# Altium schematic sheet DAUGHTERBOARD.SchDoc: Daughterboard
size A3; DocumentNumber: 3; SheetNumber: 3; SheetTotal: 6
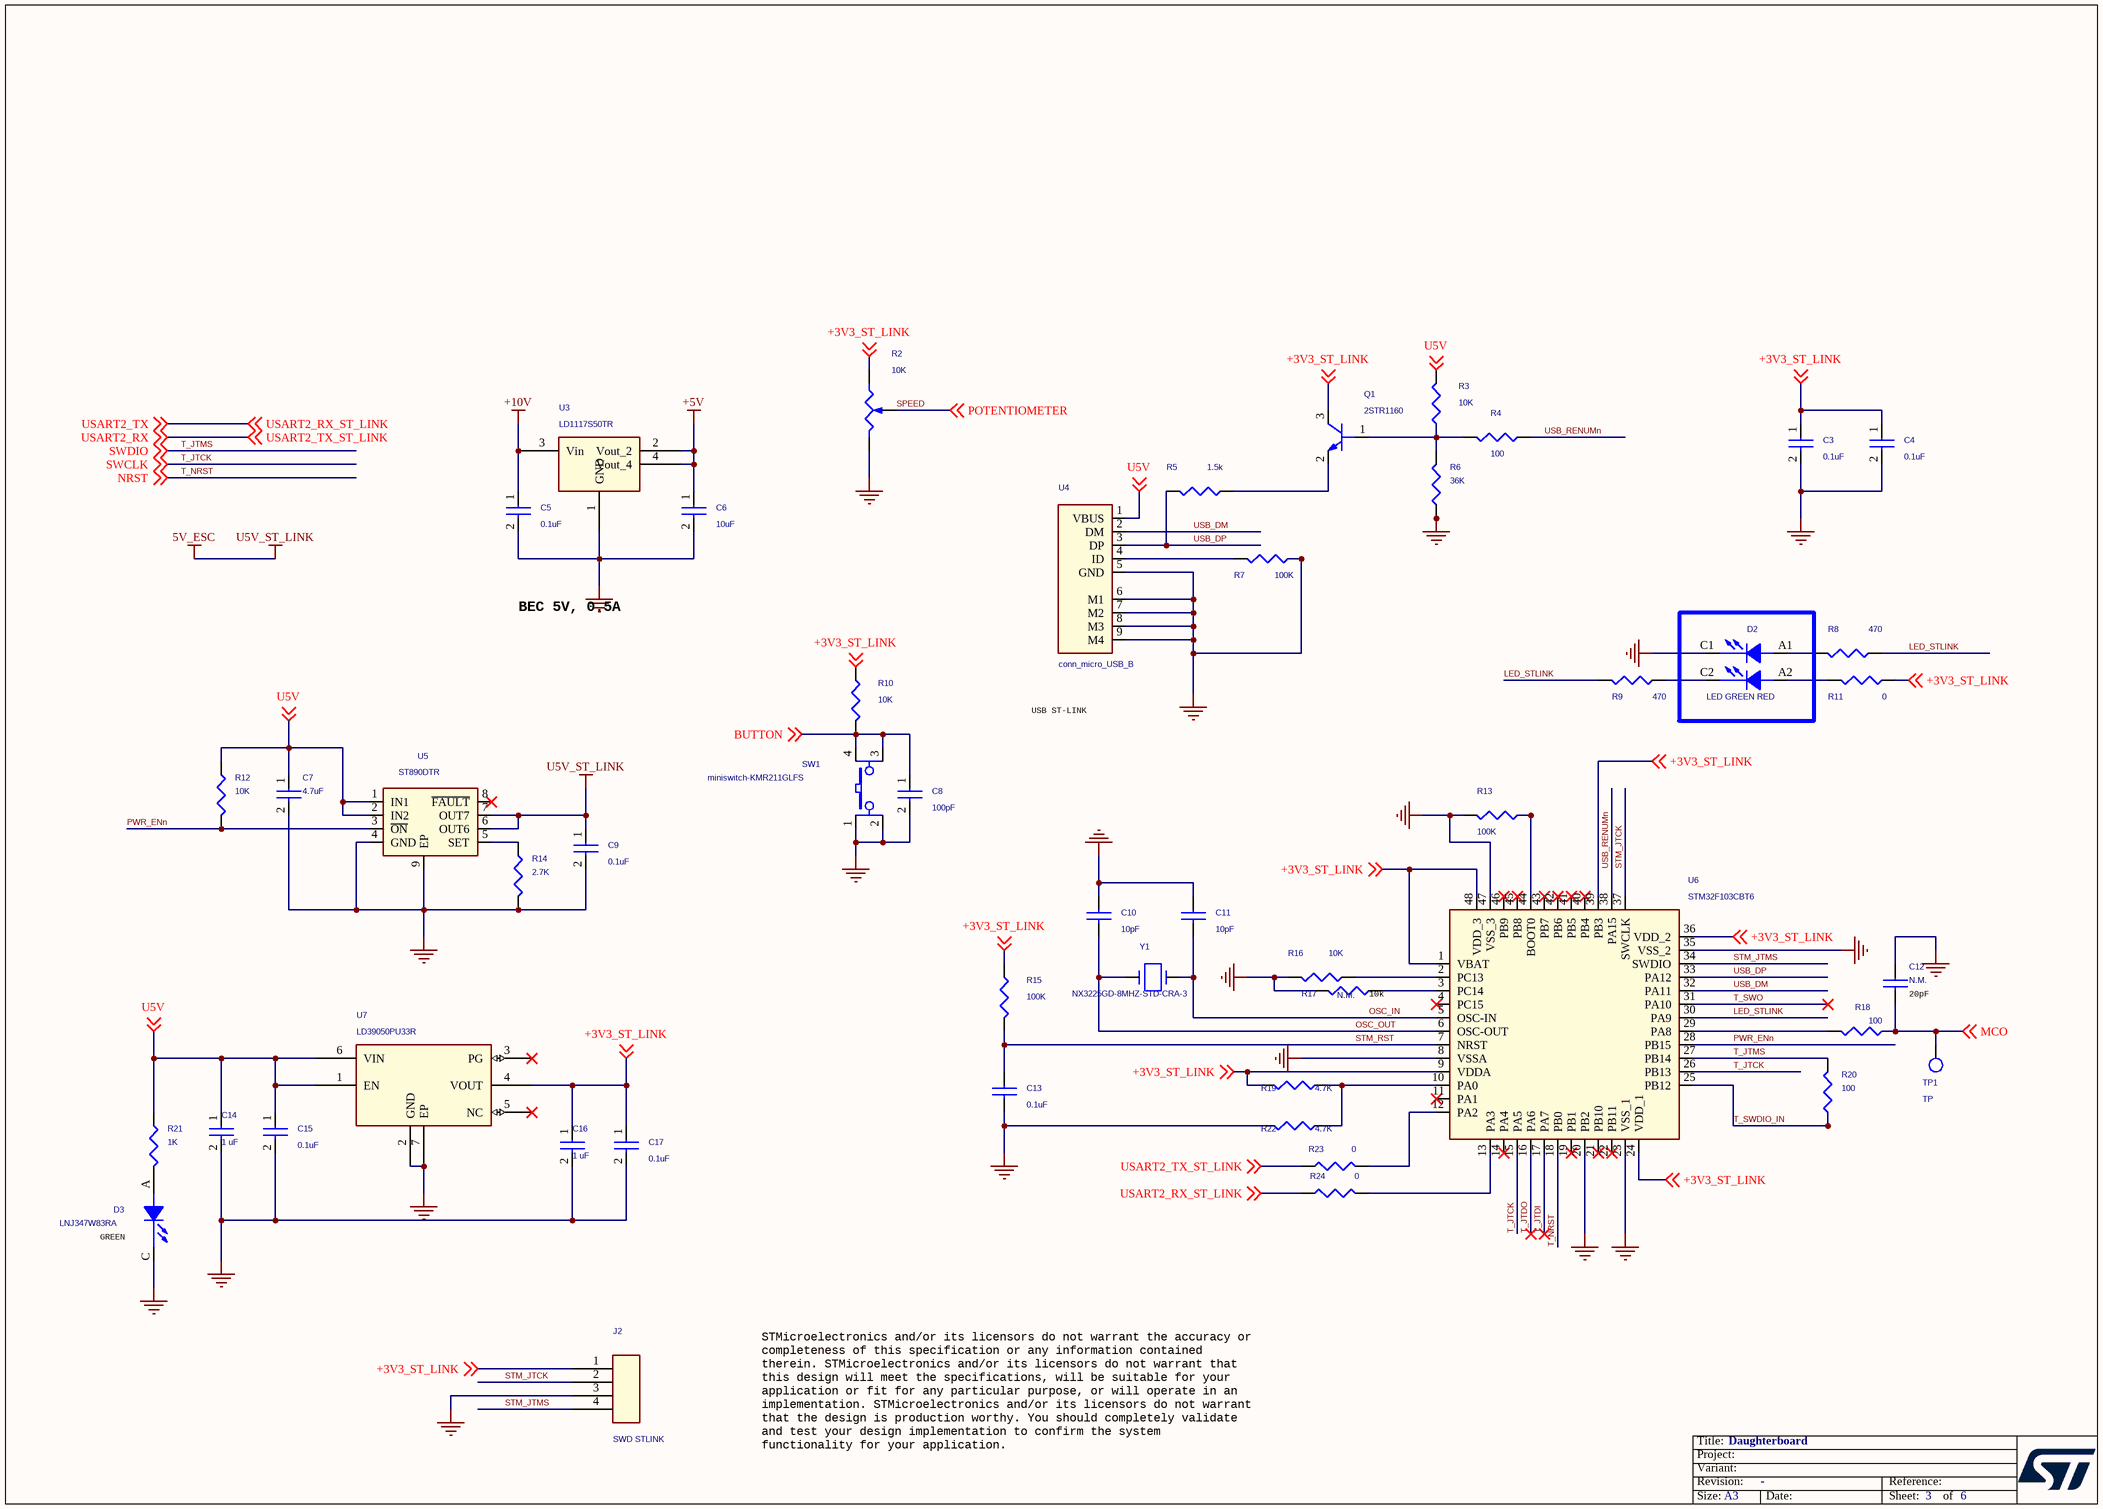
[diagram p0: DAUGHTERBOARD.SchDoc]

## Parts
C3  0.1uF  [C_0402]
C4  0.1uF  [C_0402]
C5  0.1uF  [C_0402]
C6  10uF  [C_0805]
C7  4.7uF  [C_0805]
C8  100pF  [C_0402]
C9  0.1uF  [C_0402]
C10  10pF  [C_0402]
C11  10pF  [C_0402]
C12  N.M.  [C_0402]
C13  0.1uF  [C_0402]
C14  1 uF  [C_0603]
C15  0.1uF  [C_0603]
C16  1 uF  [C_0603]
C17  0.1uF  [C_0402]
D2  LED GREEN RED  [Led_bicolor_3528-PLCC-4]
D3  LNJ347W83RA  [D_0402_Led_green]
J2  SWD STLINK  [strip4_100m_v]
Q1  2STR1160  [sot23-3p97_255x140l40x40n]
R2  10K  [trimmer-3386P_T]
R3  10K  [R_0402]
R4  100  [R_0402]
R5  1.5k  [R_0402]
R6  36K  [R_0402]
R7  100K  [R_0402]
R8  470  [R_0402]
R9  470  [R_0402]
R10  10K  [R_0402]
R11  0  [R_0402]
R12  10K  [R_0402]
R13  100K  [R_0402]
R14  2.7K  [R_0402]
R15  100K  [R_0402]
R16  10K  [R_0402]
R17  N.M.  [R_0402]
R18  100  [R_0402]
R19  4.7K  [R_0402]
R20  100  [R_0402]
R21  1K  [R_0402]
R22  4.7K  [R_0402]
R23  0  [JUMPER_0603_DROP]
R24  0  [JUMPER_0603_DROP]
SW1  miniswitch-KMR211GLFS  [switch_SMT_4_2x2_8mm]
TP1  TP  [test_point_100_smd]
U3  LD1117S50TR  [sot223-4p230_700x190l65x72]
U4  conn_micro_USB_B  [conn_micro_USB_B_SMD]
U5  ST890DTR  [son9p65_300x300x90l30x30t240-1]
U6  STM32F103CBT6  [qfp48p50_900x900x160l60x22n]
U7  LD39050PU33R  [son7p95_300x300x100l40x34t23-1]
Y1  NX3225GD-8MHZ-STD-CRA-3  [xtaldfn2_320x250x100l130x230]

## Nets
5V_ESC: C9.1 U5.6(OUT6) U5.7(OUT7)  [also labelled U5V_ST_LINK]
+5V: C6.1 U3.2(Vout_2) U3.4(Vout_4)
+10V: C5.1 U3.3(Vin)
GND: C3.2 C4.2 C5.2 C6.2 C7.2 C8.2 C9.2 C10.1 C11.1 C12.1 C13.2 C14.2 C15.2 C16.2 C17.2 D2.C1(CATHODE1) D3.C(CATHODE) J2.3 R2.1(A) R6.1 R7.1 R13.2 R14.2 R16.2 R17.2 R22.2 SW1.1 SW1.2 U3.1(GND) U4.5(GND) U4.6(M1) U4.7(M2) U4.8(M3) U4.9(M4) U5.4(GND) U5.9(EP) U6.8(VSSA) U6.20(PB2) U6.23(VSS_1) U6.35(VSS_2) U6.47(VSS_3) U7.2(GND) U7.7(EP)
+3V3_ST_LINK: C3.1 C4.1 C16.1 C17.1 J2.1 Q1.3(C) R2.3(B) R10.1 R11.1 R15.1 R19.2 U6.1(VBAT) U6.9(VDDA) U6.24(VDD_1) U6.36(VDD_2) U6.39(PB3) U6.48(VDD_3) U7.4(VOUT) ; off-sheet +3V3_ST_LINK
BUTTON: C8.1 R10.2 SW1.3 SW1.4 ; off-sheet BUTTON
LED_STLINK: R8.1 R9.2 U6.30(PA9)
MCO: C12.2 R18.1 TP1.1 ; off-sheet MCO
OSC_IN: C11.2 U6.5(OSC-IN) Y1.1
OSC_OUT: C10.2 U6.6(OSC-OUT) Y1.2
PWR_ENn: R12.2 U5.3(~{ON}) U6.28(PB15)
SPEED: R2.2(WIPER) ; off-sheet POTENTIOMETER  [also labelled POTENTIOMETER]
STM_JTCK: J2.2 U6.37(SWCLK)
STM_JTMS: J2.4 U6.34(SWDIO)
STM_RST: C13.1 R15.2 U6.7(NRST)
T_JTCK: U6.15(PA5) U6.26(PB13) ; off-sheet SWCLK  [also labelled SWCLK]
T_JTDI: U6.17(PA7)
T_JTDO: U6.16(PA6)
T_JTMS: R20.2 U6.27(PB14) ; off-sheet SWDIO  [also labelled SWDIO]
T_NRST: U6.18(PB0) ; off-sheet NRST  [also labelled NRST]
T_SWDIO_IN: R20.1 U6.25(PB12)
T_SWO: U6.31(PA10)
U5V: C7.1 C14.1 C15.1 R3.2 R12.1 R21.1 U4.1(VBUS) U5.1(IN1) U5.2(IN2) U7.1(EN) U7.6(VIN) ; off-sheet U5V
USART2_RX: R23.1 ; off-sheet USART2_TX_ST_LINK, off-sheet USART2_RX  [also labelled USART2_TX_ST_LINK]
USART2_RX_ST_LINK: R24.1 ; off-sheet USART2_RX_ST_LINK, off-sheet USART2_TX  [also labelled USART2_TX]
USB_DM: U4.2(DM) U6.32(PA11)
USB_DP: R5.2 U4.3(DP) U6.33(PA12)
USB_RENUMn: R4.1 U6.38(PA15)
NetD2_A1: D2.A1(ANODE1) R8.2
NetD2_A2: D2.A2(ANODE2) R11.2
NetD2_C2: D2.C2(CATHODE2) R9.1
NetD3_A: D3.A(ANODE) R21.2
NetQ1_1: Q1.1(B) R3.1 R4.2 R6.2
NetQ1_2: Q1.2(E) R5.1
NetR7_2: R7.2 U4.4(ID)
NetR13_1: R13.1 U6.44(BOOT0)
NetR14_1: R14.1 U5.5(SET)
NetR16_1: R16.1 U6.2(PC13)
NetR17_1: R17.1 U6.3(PC14)
NetR18_2: R18.2 U6.29(PA8)
NetR19_1: R19.1 R22.1 U6.10(PA0)
NetR23_2: R23.2 U6.12(PA2)
NetR24_2: R24.2 U6.13(PA3)

Not connected (* = marked no-connect by the designer): U5 8(~{FAULT})*; U6 4(PC15)* 11(PA1)* 14(PA4)* 19(PB1)* 21(PB10)* 22(PB11)* 40(PB4)* 41(PB5)* 42(PB6)* 43(PB7)* 45(PB8)* 46(PB9)*; U7 3(PG)* 5(NC)*

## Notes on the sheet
- BEC 5V, 0.5A
- USB ST-LINK
- (near R17) 10k
- (near C12) 20pF
- (near D3) GREEN
- STMicroelectronics and/or its licensors do not warrant the accuracy or
  completeness of this specification or any information contained
  therein. STMicroelectronics and/or its licensors do not warrant that
  this design will meet the specifications, will be suitable for your
  application or fit for any particular purpose, or will operate in an
  implementation. STMicroelectronics and/or its licensors do not warrant
  that the design is production worthy. You should completely validate
  and test your design implementation to confirm the system
  functionality for your application.

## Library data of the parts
C3-C5 C9 = CAP_Dup1: CAP CER 0.1UF 16V X7R 0402; Manufacturer PN: 885012205037; Manufacturer: Wurth Electronics Inc.; PART_NUMBER: CAP-00000053; CLASS: DISCRETE; Tolerance: 10%; Dielectric Type: Capacitors
C6 = CAP_Dup1: CAP CER 10UF 16V X5R 0805; Manufacturer PN: 885012107014; Manufacturer: Wurth Electronics Inc.; PART_NUMBER: TMP-409; CLASS: DISCRETE; Tolerance: 20%; Dielectric Type: Capacitors
C7 = CAP_Dup1: CAP CER 4.7UF 16V X5R 0805; PART_NUMBER: TMP-410; Manufacturer: Wurth Electronics Inc.; Manufacturer PN: 885012107013; Dielectric Type: Capacitors; Tolerance: 20%; CLASS: DISCRETE
C8 = CAP_Dup1: CAP CER 100PF 10V C0G/NP0 0402; PART_NUMBER: TMP-412; Manufacturer: Wurth Electronics Inc.; Manufacturer PN: 885012005013; Dielectric Type: Capacitors; Temperature Coefficient: C0G, NP0; Tolerance: 5%; CLASS: DISCRETE
C10 C11 = CAP_7: CAP CER 10PF 10V C0G/NP0 0402; PART_NUMBER: TMP-395; Manufacturer: Wurth Electronics Inc.; Manufacturer PN: 885012005007; Dielectric Type: Capacitors; Temperature Coefficient: C0G, NP0; Tolerance: 5%; CLASS: DISCRETE
C12 = CAP_6: CAP CER 0402-NOT MOUNTED; PART_NUMBER: TMP-408; CLASS: DISCRETE
C13 = CAP_8: CAP CER 0.1UF 16V X7R 0402; PART_NUMBER: CAP-00000053; Manufacturer: Wurth Electronics Inc.; Manufacturer PN: 885012205037; Dielectric Type: Capacitors; Tolerance: 10%; CLASS: DISCRETE
C14 C16 = CAP_Dup1: CAP CER 1UF 16V X5R 0603; PART_NUMBER: TMP-302; Manufacturer: Yageo; Manufacturer PN: CC0603KRX5R7BB105; Dielectric Type: Capacitors; Tolerance: 10%; CLASS: DISCRETE
C15 = CAP_Dup1: CAP CER 0.1UF 16V X7R 0603; Manufacturer PN: 885012206046; Manufacturer: Wurth Electronics Inc.; PART_NUMBER: CAP-00000052; CLASS: DISCRETE; Tolerance: 10%; Dielectric Type: Capacitors
C17 = CAP_Dup1: CAP CER 0.1UF 16V X7R 0402; PART_NUMBER: CAP-00000053; Manufacturer: Wurth Electronics Inc.; Manufacturer PN: 885012205037; Dielectric Type: Capacitors; Tolerance: 10%; CLASS: DISCRETE
D2 = LED_BICOLOR: LED GREEN/RED CLEAR 4PLCC SMD; PART_NUMBER: TMP-705; Manufacturer: Wurth Electronics Inc.; Manufacturer PN: 150141RV73100; CLASS: DISCRETE
D3 = LED: LED GREEN 0402 SMD; Manufacturer PN: 16-213SYGC/S530-E3/TR8; Manufacturer: Everlight Electronics; PART_NUMBER: TMP-187; CLASS: DISCRETE
J2 = CON4: SOLDER PADS
Q1 = BJT_NPN_BEC: TRANS NPN 60V 1A SOT-23; PART_NUMBER: TMP-433; Manufacturer: STMicroelectronics; CLASS: DISCRETE
R2 = POT: TRIMMER 10K OHM 0.5W PC PIN; PART_NUMBER: TMP-491; Manufacturer: Bourns Inc.; Manufacturer PN: 3386P-1-103TLF; Temperature Coefficient: 100ppm/C; Tolerance: 10%; Rated Power: 0.5W, 1/2W; CLASS: DISCRETE
R3 R12 = RES: RES SMD 10K OHM 1% 1/16W 0402; Manufacturer PN: RC0402FR-0710KL; Manufacturer: Yageo; PART_NUMBER: TMP-396; CLASS: DISCRETE; Rated Power: 0.063W, 1/16W; Temperature Coefficient: 100ppm/C
R4 R8 R20 = RES: RES SMD 100 OHM 1% 1/16W 0402; PART_NUMBER: TMP-406; Manufacturer: TE Connectivity Passive Product; Manufacturer PN: CRG0402F100R; Temperature Coefficient: 100ppm/C; Rated Power: 0.063W, 1/16W; CLASS: DISCRETE
R5 = RES: RES SMD 1.5K OHM 1% 1/16W 0402; PART_NUMBER: TMP-393; Manufacturer: Yageo; Manufacturer PN: RC0402FR-071K5L; Temperature Coefficient: 100ppm/C; Rated Power: 0.063W, 1/16W; CLASS: DISCRETE
R6 = RES: RES SMD 36K OHM 1% 1/16W 0402; Manufacturer PN: RC0402FR-0736KL; Manufacturer: Yageo; PART_NUMBER: TMP-436; CLASS: DISCRETE; Rated Power: 0.063W, 1/16W; Temperature Coefficient: 100ppm/C
R7 R13 = RES: RES SMD 100K OHM 1% 1/16W 0402; Manufacturer PN: CRG0402F100K; Manufacturer: TE Connectivity Passive Product; PART_NUMBER: TMP-405; CLASS: DISCRETE; Rated Power: 0.063W, 1/16W; Temperature Coefficient: 100ppm/C
R9 R18 = RES: RES SMD 100 OHM 1% 1/16W 0402; Manufacturer PN: CRG0402F100R; Manufacturer: TE Connectivity Passive Product; PART_NUMBER: TMP-406; CLASS: DISCRETE; Rated Power: 0.063W, 1/16W; Temperature Coefficient: 100ppm/C
R10 R16 = RES: RES SMD 10K OHM 1% 1/16W 0402; PART_NUMBER: TMP-396; Manufacturer: Yageo; Manufacturer PN: RC0402FR-0710KL; Temperature Coefficient: 100ppm/C; Rated Power: 0.063W, 1/16W; CLASS: DISCRETE
R11 = RES: RES SMD 0 OHM JUMPER 1/16W 0402; Manufacturer PN: CRCW04020000Z0ED; Manufacturer: Vishay Dale; PART_NUMBER: RES-00000073; CLASS: DISCRETE; Rated Power: 0.063W, 1/16W
R14 = RES: RES SMD 2.7K OHM 1% 1/16W 0402; PART_NUMBER: TMP-411; Manufacturer: Yageo; Manufacturer PN: RC0402FR-072K7L; Temperature Coefficient: 100ppm/C; Rated Power: 0.063W, 1/16W; CLASS: DISCRETE
R15 = RES: RES SMD 100K OHM 1% 1/16W 0402; PART_NUMBER: TMP-405; Manufacturer: TE Connectivity Passive Product; Manufacturer PN: CRG0402F100K; Temperature Coefficient: 100ppm/C; Rated Power: 0.063W, 1/16W; CLASS: DISCRETE
R17 = RES: RES SMD 0402 - NOT MOUNTED; PART_NUMBER: TMP-404; CLASS: DISCRETE
R19 R22 = RES: RES SMD 4.7K OHM 1% 1/16W 0402; PART_NUMBER: TMP-403; Manufacturer: TE Connectivity Passive Product; Manufacturer PN: CRG0402F4K7; Temperature Coefficient: 100ppm/C; Rated Power: 0.063W, 1/16W; CLASS: DISCRETE
R21 = RES: RES SMD 1K OHM 1% 1/16W 0402; PART_NUMBER: TMP-352; Manufacturer: Yageo; Manufacturer PN: RC0402FR-071KL; Temperature Coefficient: 100ppm/C; Rated Power: 0.063W, 1/16W; CLASS: DISCRETE; ALT_SYMBOLS: r_0402_hd
R23 = RES: RES SMD 0 OHM JUMPER 1/10W 0603; Manufacturer PN: ERJ-3GEY0R00V; Manufacturer: Panasonic Electronic Components; PART_NUMBER: RES-00000056; CLASS: DISCRETE; Rated Power: 0.1W, 1/10W
R24 = RES: RES SMD 0 OHM JUMPER 1/10W 0603; PART_NUMBER: RES-00000056; Manufacturer: Panasonic Electronic Components; Manufacturer PN: ERJ-3GEY0R00V; Rated Power: 0.1W, 1/10W; CLASS: DISCRETE
SW1 = PUSHBUTTON-SPST-2: SWITCH TACTILE SPST-NO 0.05A 32V; Manufacturer: C&K; PART_NUMBER: TMP-285; CLASS: DISCRETE
TP1 = TESTPOINT: TEST POINT 1MM  SMD PADSTASCK; PART_NUMBER: TMP-386; CLASS: IO
U3 = LD1117SxxxTR_0: IC REG LINEAR 5V 800MA SOT223; Manufacturer: STMicroelectronics; PART_NUMBER: TMP-381
U4 = USB_MICRO: CONN RCPT 5POS MICRO USB R/A; Manufacturer PN: 0473460001; Manufacturer: Molex, LLC; PART_NUMBER: TMP-434; CLASS: IO
U5 = ST890DTR: IC PWR SWITCH 1.2A HISIDE 8-DFN; Manufacturer: STMicroelectronics; PART_NUMBER: TMP-432; Supply Voltage: Not Required
U6 = STM32F103CBT6: IC MCU 32BIT 128KB FLASH 48LQFP; PART_NUMBER: TMP-399; Manufacturer: STMicroelectronics; Supply Voltage: 2 V ~ 3.6 V
U7 = LD39050PU33R: IC REG LINEAR 3.3V 500MA 6DFN; PART_NUMBER: TMP-358; Manufacturer: STMicroelectronics
Y1 = crystal: CRYSTAL 8.0000MHZ 8PF SMD; Manufacturer: NDK America, Inc.; PART_NUMBER: TMP-435; CLASS: DISCRETE; Frequency Tolerance: 50ppm; Frequency Stability: 150ppm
